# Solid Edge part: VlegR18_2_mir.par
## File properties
Author: Türk
Template: Iso Part.par
Last saved by: Türk
Revision: 2
Application: Solid Edge
Accuracy: 0,990
Username: Türk
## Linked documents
VlegR18_2.par
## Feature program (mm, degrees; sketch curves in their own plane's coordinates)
part copy "CopiedPart_1"
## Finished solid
Body 1: solid body, 140 faces, 339 edges, 182 vertices, 2 internal voids.
  Faces by surface: cylinder 65, plane 24, torus 23, blend 14, cone 9, spun 5
  Edges by curve: intersection 145, circle 130, line 64
Bounding box of the edges (mm; curved faces can reach further): 200.000 x 457.200 x 457.200, from (-100, -228.6, -228.6) to (100, 228.6, 228.6).
Cylindrical faces by radius (mm): R4 x16, R6 x5, R15 x5, R25 x16, R62.5 x1, R80 x8, R174.2298 x8, R203.6 x2, R216.1 x2, R228.6 x2
Conical faces (half-angle, radius in mm at the cone's reference point): 2.0106 deg R178.4522 x2, 5.4632 deg R201.6202 x2, 54.824 deg R174.2298 x1, 54.824 deg R203.0605 x2, 54.824 deg R203.6 x1, 83.4677 deg R62.5 x1
Toroidal faces (ring radius, tube radius in mm): R79 r1 x7, R136.945 r40 x8, R205.6 r2 x2, R214.1 r2 x2, R226.6 r2 x4
Planar faces by outward normal: +x 4, -x 4, oblique 16
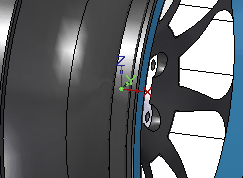
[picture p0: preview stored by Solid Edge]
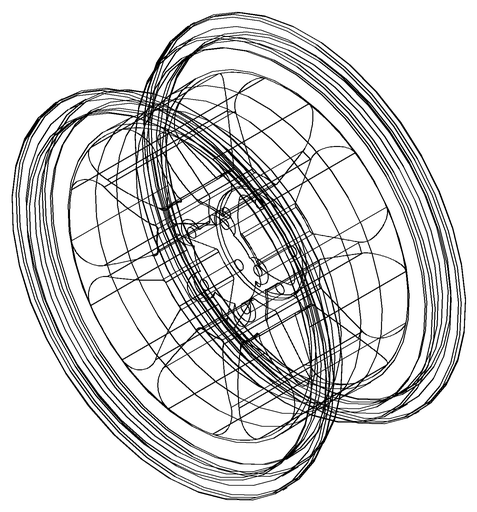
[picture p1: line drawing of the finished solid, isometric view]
